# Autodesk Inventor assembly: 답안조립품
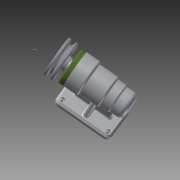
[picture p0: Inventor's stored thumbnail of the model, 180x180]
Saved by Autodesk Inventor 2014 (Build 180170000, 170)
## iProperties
Created: 2016-06
Part Number: 답안조립품
Document SubType Name: Assembly
Designer: SEC
Author: SEC
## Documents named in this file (12)
- C:\Documents and Settings\SEC\바탕 화면\460607V1008\답안조립품.iam
- C:\Documents and Settings\SEC\바탕 화면\460607V1008\본체.ipt
- C:\Documents and Settings\SEC\바탕 화면\460607V1008\어댑터슬리브.ipt
- C:\Documents and Settings\SEC\바탕 화면\460607V1008\베어링 6004.ipt
- C:\Documents and Settings\SEC\바탕 화면\460607V1008\베어링 51202.ipt
- C:\Documents and Settings\SEC\바탕 화면\460607V1008\축.ipt
- C:\Documents and Settings\SEC\바탕 화면\460607V1008\볼트 M4 x 12.ipt
- C:\Documents and Settings\SEC\바탕 화면\460607V1008\커버.ipt
- C:\Documents and Settings\SEC\바탕 화면\460607V1008\멈춤나사 M3x8.ipt
- C:\Documents and Settings\SEC\바탕 화면\460607V1008\V벨트풀리.ipt
- C:\Documents and Settings\SEC\바탕 화면\460607V1008\오일 실.ipt
- C:\Documents and Settings\SEC\바탕 화면\460607V1008\키 5 x 5 x 16.ipt
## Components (6 placed, 2 different names)
1. ISO 4762 M4 x 12:1
2. V벨트풀리:1 — 플러쉬:1
3. ISO 4762 M4 x 12:2
4. ISO 4762 M4 x 12:3
5. ISO 4762 M4 x 12:4
6. ISO 4762 M4 x 12:5
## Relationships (1: Flush 1)
- 플러쉬:1 [Flush]: V벨트풀리:1
